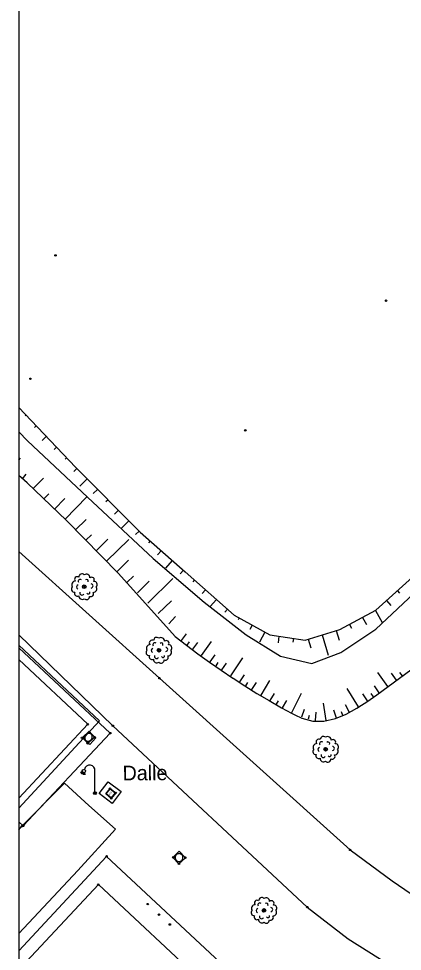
# Model space of a CAD drawing. Extents: x 344013 to 344423, y 298505 to 298795.
# Drawn here: x 344012.9 to 344038.9, y 298691.1 to 298754.4 of the extents above; entities that cross this region are included whole.
import ezdxf

# ---------------------------------------------------------------- set-up
doc = ezdxf.new("R2010")
doc.units = 0
for name, color, linetype in [('Default', 7, 'Continuous'), ('DH_CADRE -CARTOUCHE', 7, 'Continuous'), ('IMM_VOIRIE VOIE FERREE', 7, 'Continuous'), ('PC_CONCRETE', 7, 'Continuous'), ('PS_BOLT', 7, 'Continuous'), ('PS_CONST', 7, 'Continuous'), ('PS_KOTE', 7, 'Continuous'), ('PS_PLATE', 7, 'Continuous'), ('RES_ELECTRICITE', 7, 'Continuous'), ('TOPO_POINT', 7, 'Continuous'), ('TOPO_TALUS-TERRAIN NATUREL', 7, 'Continuous'), ('VOIRIE_BORDURE', 7, 'Continuous'), ('VOIRIE_ESPACE VERT', 7, 'Continuous')]:
    doc.layers.add(name, color=color, linetype=linetype)

# ---------------------------------------------------------------- blocks, each defined once
blk = doc.blocks.new('REG_INC')
at = {"layer": 'Default'}
for p, q in [((0, 1), (1, 1)), ((0, 0), (0, 1)), ((1, 0), (0, 0)), ((1, 1), (1, 0))]:
    blk.add_line(p, q, dxfattribs=at)
for start, end in [(135.0055, 180.0055), (180.0066, 225.0066), (90.0058, 135.0058), (225.0069, 270.0069), (45.0069, 90.0069), (270.0058, 315.0058), (0.0066, 45.0066), (315.0055, 0.0055)]:
    blk.add_arc((0.5, 0.5), 0.44, start, end, dxfattribs=at)
blk = doc.blocks.new('RES_ELECTRICITE')
at = {"layer": 'RES_ELECTRICITE'}
for points in [[(0, 0), (0, 1), (1, 1), (1, 0)], [(0.05, 0.05), (0.05, 0.95), (0.95, 0.95), (0.95, 0.05)]]:
    blk.add_lwpolyline(points, close=True, dxfattribs=at)
blk.add_text('EEC', height=0.2, dxfattribs=at).set_placement((0.24, 0.46))
blk = doc.blocks.new('EDF1')
at = {"layer": 'Default'}
for points in [[(-0.855, 1.462), (-0.985, 1.373)], [(-0.83, 1.422), (-0.931, 1.303)], [(-0.793, 1.397), (-0.86, 1.257)], [(-0.753, 1.388), (-0.781, 1.235)], [(-0.701, 1.4), (-0.684, 1.241)], [(0, 0.1), (0, 1.5)]]:
    blk.add_lwpolyline(points, dxfattribs=at)
for centre, radius in [((-0.75, 1.5), 0.112), ((0, 0), 0.1)]:
    blk.add_circle(centre, radius, dxfattribs=at)
blk.add_arc((-0.35, 1.55), 0.354, 351.8699, 171.8699, dxfattribs=at)
blk = doc.blocks.new('POINT_DISPLAY')
at = {"layer": 'Default'}
blk.add_circle((0, 0), 0.05, dxfattribs=at)
blk = doc.blocks.new('ARB1')
at = {"layer": 'Default'}
blk.add_circle((0, 0), 0.122, dxfattribs=at)
for centre, radius, start, end in [((-0.471, 0.503), 0.183, 53.95544, 222.20655), ((-0.153, 0.664), 0.211, 43.69255, 183.5969), ((0.139, 0.613), 0.241, 358.45835, 125.19284), ((0.501, 0.468), 0.183, 325.14445, 131.01755), ((-0.613, 0.139), 0.241, 88.45835, 215.19284), ((-0.373, -0.024), 0.149, 103.70924, 242.34652), ((-0.276, 0.37), 0.134, 52.43963, 209.54959), ((0.164, 0.38), 0.112, 330.58954, 133.71274), ((0.458, 0.052), 0.137, 276.62143, 88.96702), ((0.613, -0.139), 0.241, 268.45835, 35.19284), ((0.664, 0.153), 0.211, 313.69255, 93.5969), ((-0.664, -0.153), 0.211, 133.69255, 273.5969), ((-0.478, -0.443), 0.19, 155.22426, 300.93774), ((-0.139, -0.613), 0.241, 178.45835, 305.19284), ((-0.163, -0.42), 0.148, 159.53711, 338.16632), ((0.271, -0.38), 0.112, 210.58954, 13.71274), ((0.448, -0.483), 0.188, 243.13234, 33.02965), ((0.153, -0.664), 0.211, 223.69255, 3.5969)]:
    blk.add_arc(centre, radius, start, end, dxfattribs=at)

msp = doc.modelspace()

# ---------------------------------------------------------------- linework, layer by layer
at = {"layer": 'DH_CADRE -CARTOUCHE'}
for points in [[(344012.906, 298504.876), (344422.906, 298504.876), (344422.906, 298791.876), (344012.906, 298791.876)], [(344018.318, 298695.613), (344013.095, 298690.028), (344027.812, 298676.264), (344033.029, 298681.855)]]:
    msp.add_lwpolyline(points, close=True, dxfattribs=at)
msp.add_lwpolyline([(344012.906, 298701.467), (344017.596, 298706.489), (344012.906, 298710.894)], dxfattribs=at)
at = {"layer": 'IMM_VOIRIE VOIE FERREE'}
msp.add_line((344012.906, 298699.331), (344013.125, 298699.572), dxfattribs=at)
msp.add_lwpolyline([(344013.125, 298699.572), (344016.018, 298702.503), (344017.66, 298700.981), (344019.475, 298699.365), (344016.927, 298696.559), (344012.906, 298692.279)], dxfattribs=at)
at = {"layer": 'PC_CONCRETE'}
msp.add_lwpolyline([(344012.906, 298726.346), (344013.507, 298725.743), (344017.568, 298721.906), (344022.045, 298717.759), (344025.494, 298714.787), (344028.346, 298712.557), (344030.671, 298711.106), (344032.803, 298710.622), (344034.772, 298711.359), (344037.136, 298712.96), (344040.107, 298715.733), (344043.693, 298719.182), (344046.555, 298722.034), (344068.09, 298743.955), (344075.914, 298752.239), (344077.673, 298754.306), (344096.592, 298773.384)], dxfattribs=at)
at = {"layer": 'PS_BOLT'}
for points in [[(344012.906, 298699.872), (344013.218, 298699.591), (344019.121, 298705.889), (344012.906, 298711.69)], [(344019.243, 298701.118), (344018.363, 298701.783), (344018.989, 298702.576), (344019.86, 298701.919), (344019.243, 298701.118)], [(344012.906, 298688.945), (344027.856, 298674.963), (344034.929, 298682.543), (344018.872, 298697.524), (344012.906, 298691.117)]]:
    msp.add_lwpolyline(points, dxfattribs=at)
at = {"layer": 'PS_KOTE'}
msp.add_lwpolyline([(344018.134, 298705.577), (344017.731, 298705.13), (344017.297, 298705.527), (344017.699, 298705.973), (344018.134, 298705.577)], dxfattribs=at)
at = {"layer": 'PS_PLATE'}
msp.add_lwpolyline([(344012.906, 298711.865), (344018.392, 298706.728), (344012.906, 298700.798)], dxfattribs=at)
at = {"layer": 'TOPO_TALUS-TERRAIN NATUREL'}
for p, q in [((344013.398, 298727.477), (344013.348, 298727.43)), ((344014.089, 298726.754), (344013.972, 298726.643)), ((344014.78, 298726.031), (344014.507, 298725.771)), ((344015.471, 298725.308), (344015.312, 298725.156)), ((344012.906, 298724.431), (344013.021, 298724.571)), ((344016.163, 298724.585), (344016.069, 298724.496)), ((344013.159, 298723.165), (344013.42, 298723.482)), ((344016.856, 298723.864), (344016.641, 298723.651)), ((344013.9, 298722.495), (344014.595, 298723.213)), ((344017.56, 298723.154), (344017.058, 298722.656)), ((344014.619, 298721.8), (344014.949, 298722.14)), ((344018.265, 298722.444), (344017.971, 298722.153)), ((344015.338, 298721.104), (344016.034, 298721.823)), ((344016.057, 298720.409), (344017.525, 298721.927)), ((344018.969, 298721.734), (344018.83, 298721.596)), ((344019.674, 298721.024), (344019.41, 298720.763)), ((344016.761, 298719.698), (344017.476, 298720.401)), ((344020.379, 298720.314), (344019.879, 298719.818)), ((344021.083, 298719.604), (344020.846, 298719.369)), ((344017.462, 298718.985), (344017.839, 298719.356)), ((344018.163, 298718.272), (344018.96, 298719.055)), ((344018.865, 298717.558), (344020.377, 298719.046)), ((344021.83, 298718.939), (344021.714, 298718.807)), ((344022.581, 298718.279), (344022.337, 298718.001)), ((344019.566, 298716.845), (344020.364, 298717.63)), ((344023.333, 298717.619), (344022.871, 298717.092)), ((344024.085, 298716.959), (344023.866, 298716.71)), ((344020.27, 298716.135), (344020.689, 298716.551)), ((344021.679, 298714.714), (344023.359, 298716.381)), ((344024.833, 298716.295), (344024.717, 298716.165)), ((344020.975, 298715.425), (344021.771, 298716.214)), ((344025.581, 298715.631), (344025.36, 298715.383)), ((344038.612, 298715.559), (344038.754, 298715.401)), ((344022.383, 298714.004), (344023.27, 298714.883)), ((344026.328, 298714.966), (344025.91, 298714.496)), ((344037.869, 298714.888), (344038.17, 298714.556)), ((344023.103, 298713.31), (344023.539, 298713.803)), ((344027.075, 298714.301), (344026.897, 298714.101)), ((344036.241, 298713.751), (344036.504, 298713.263)), ((344037.122, 298714.226), (344037.571, 298713.394)), ((344027.874, 298713.709), (344027.806, 298713.585)), ((344028.749, 298713.224), (344028.589, 298712.935)), ((344035.361, 298713.276), (344035.5, 298713.019)), ((344029.624, 298712.739), (344029.249, 298712.063)), ((344033.502, 298712.561), (344033.921, 298711.175)), ((344034.46, 298712.85), (344034.658, 298712.193)), ((344030.572, 298712.471), (344030.507, 298712.023)), ((344031.562, 298712.327), (344031.524, 298712.065)), ((344032.545, 298712.272), (344032.724, 298711.68))]:
    msp.add_line(p, q, dxfattribs=at)
for points in [[(344012.906, 298727.992), (344016.77, 298723.95), (344021.159, 298719.528), (344024.211, 298716.849), (344027.522, 298713.904), (344029.942, 298712.562), (344032.347, 298712.213), (344034.711, 298712.926), (344037.156, 298714.245), (344039.404, 298716.274), (344041.832, 298718.647), (344065.143, 298742.501), (344075.455, 298753.587)], [(344023.526, 298712.443), (344019.677, 298716.733), (344016.151, 298720.317), (344013.488, 298722.894), (344012.906, 298723.374)], [(344024.274, 298712.625), (344023.929, 298712.171)], [(344023.526, 298712.443), (344024.292, 298711.854), (344025.068, 298711.278), (344025.853, 298710.715), (344026.646, 298710.164), (344027.448, 298709.627), (344027.469, 298709.614), (344028.258, 298709.103), (344029.076, 298708.593), (344029.902, 298708.096), (344030.735, 298707.613), (344031.414, 298707.241), (344031.641, 298707.138), (344032.128, 298706.918), (344032.867, 298706.714), (344033.619, 298706.699), (344034.4, 298706.88), (344035.144, 298707.184), (344035.856, 298707.577), (344036.177, 298707.786), (344036.541, 298708.024), (344037.204, 298708.491), (344037.982, 298709.05), (344038.754, 298709.618), (344039.52, 298710.197)], [(344024.477, 298712.091), (344024.314, 298711.875)], [(344025.043, 298712.044), (344024.703, 298711.586)], [(344025.976, 298712.103), (344025.29, 298711.155)], [(344026.21, 298711.197), (344025.882, 298710.731)], [(344026.434, 298710.677), (344026.28, 298710.455)], [(344027, 298710.65), (344026.679, 298710.179)], [(344028.097, 298710.999), (344027.284, 298709.773)], [(344037.261, 298710.01), (344037.949, 298709.063)], [(344038.196, 298709.952), (344038.535, 298709.494)], [(344038.762, 298710), (344038.925, 298709.784)], [(344028.202, 298709.854), (344027.893, 298709.375)], [(344028.446, 298709.34), (344028.301, 298709.112)], [(344029.014, 298709.339), (344028.712, 298708.855)], [(344029.939, 298709.475), (344029.332, 298708.474)], [(344035.189, 298708.933), (344035.958, 298707.679)], [(344037.026, 298709.102), (344037.358, 298708.638)], [(344030.246, 298708.59), (344029.956, 298708.099)], [(344030.511, 298708.09), (344030.376, 298707.856)], [(344031.075, 298708.111), (344030.796, 298707.614)], [(344032.089, 298708.582), (344031.434, 298707.265)], [(344036.245, 298708.55), (344036.566, 298708.078)], [(344036.807, 298708.579), (344036.962, 298708.357)], [(344032.293, 298707.502), (344032.094, 298706.966)], [(344033.583, 298707.922), (344033.744, 298706.758)], [(344034.266, 298707.474), (344034.445, 298706.931)], [(344035.068, 298707.828), (344035.328, 298707.32)], [(344032.618, 298707.094), (344032.556, 298706.831)], [(344033.079, 298707.31), (344033.026, 298706.741)], [(344034.786, 298707.362), (344034.892, 298707.114)]]:
    msp.add_lwpolyline(points, dxfattribs=at)
at = {"layer": 'VOIRIE_BORDURE'}
for points in [[(344012.906, 298718.231), (344022.459, 298709.623), (344035.4, 298697.966), (344038.262, 298695.856), (344041.267, 298693.813), (344044.479, 298691.842), (344047.664, 298690.365), (344050.648, 298689.339), (344052.822, 298689.099), (344054.599, 298689.128), (344056.124, 298689.428), (344057.609, 298690.129), (344058.956, 298690.85), (344060.299, 298691.725), (344061.274, 298692.556), (344063.092, 298694.498), (344091.5, 298724.03), (344099.786, 298732.889), (344115.711, 298749.674), (344123.231, 298757.884), (344127.749, 298762.864), (344141.666, 298775.429), (344153.501, 298787.287)], [(344012.906, 298712.566), (344019.297, 298706.391), (344032.494, 298694.078), (344035.262, 298691.929), (344038.684, 298689.77), (344042.541, 298687.653), (344055.386, 298681.278), (344062.722, 298673.608), (344079.116, 298659.278), (344094.724, 298644.749), (344120.412, 298621.951), (344137.791, 298639.981)]]:
    msp.add_lwpolyline(points, dxfattribs=at)

# ---------------------------------------------------------------- block references
at = {"layer": 'PC_CONCRETE'}
for p, xscale, yscale, rotation in [((344017.593, 298705.193), 0.631771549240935, 0.544622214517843, 41.9256), ((344023.785, 298697.015), 0.603339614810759, 0.6060682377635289, 43.89714000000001)]:
    msp.add_blockref('REG_INC', p, dxfattribs=dict(at, xscale=xscale, yscale=yscale, rotation=rotation))
at = {"layer": 'RES_ELECTRICITE'}
msp.add_blockref('EDF1', (344018.081, 298701.821), dxfattribs=at)
at = {"layer": 'RES_ELECTRICITE', "xscale": 0.477011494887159, "yscale": 0.47613694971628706, "rotation": 50.79383999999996}
msp.add_blockref('RES_ELECTRICITE', (344019.188, 298701.463), dxfattribs=at)
at = {"layer": 'TOPO_POINT'}
for p in [(344015.407, 298738.323), (344037.842, 298735.249), (344013.703, 298729.95), (344028.288, 298726.446), (344017.358, 298715.829), (344022.427, 298711.521), (344022.459, 298709.623), (344017.596, 298706.489), (344019.297, 298706.391), (344017.201, 298705.573), (344018.063, 298705.615), (344019.121, 298705.889), (344017.593, 298705.193), (344033.74, 298704.798), (344018.081, 298701.821), (344019.107, 298702.117), (344019.49, 298701.833), (344019.188, 298701.463), (344013.125, 298699.572), (344013.218, 298699.591), (344035.4, 298697.966), (344018.872, 298697.524), (344023.397, 298697.46), (344024.22, 298697.434), (344023.785, 298697.015), (344018.303, 298695.599), (344021.67, 298694.285), (344032.494, 298694.078), (344022.433, 298693.569), (344029.556, 298693.856), (344023.165, 298692.899)]:
    msp.add_blockref('POINT_DISPLAY', p, dxfattribs=at)
at = {"layer": 'VOIRIE_ESPACE VERT'}
for p in [(344017.358, 298715.829), (344022.427, 298711.521), (344033.74, 298704.798), (344029.556, 298693.856)]:
    msp.add_blockref('ARB1', p, dxfattribs=at)

# ---------------------------------------------------------------- texts
at = {"layer": 'PS_CONST'}
msp.add_text('Dalle', height=1.0003, rotation=0.36652, dxfattribs=at).set_placement((344019.96, 298702.679))

doc.saveas('drawing.dxf')
